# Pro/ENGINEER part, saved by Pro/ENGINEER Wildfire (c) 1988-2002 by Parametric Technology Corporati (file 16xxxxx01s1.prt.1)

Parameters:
  HERSTELLER = "Hersteller"
  NB = "16XXXXX01S-1"
  NN = "16-S1"
  NT = "16 Series - Swivel - Top Plate"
